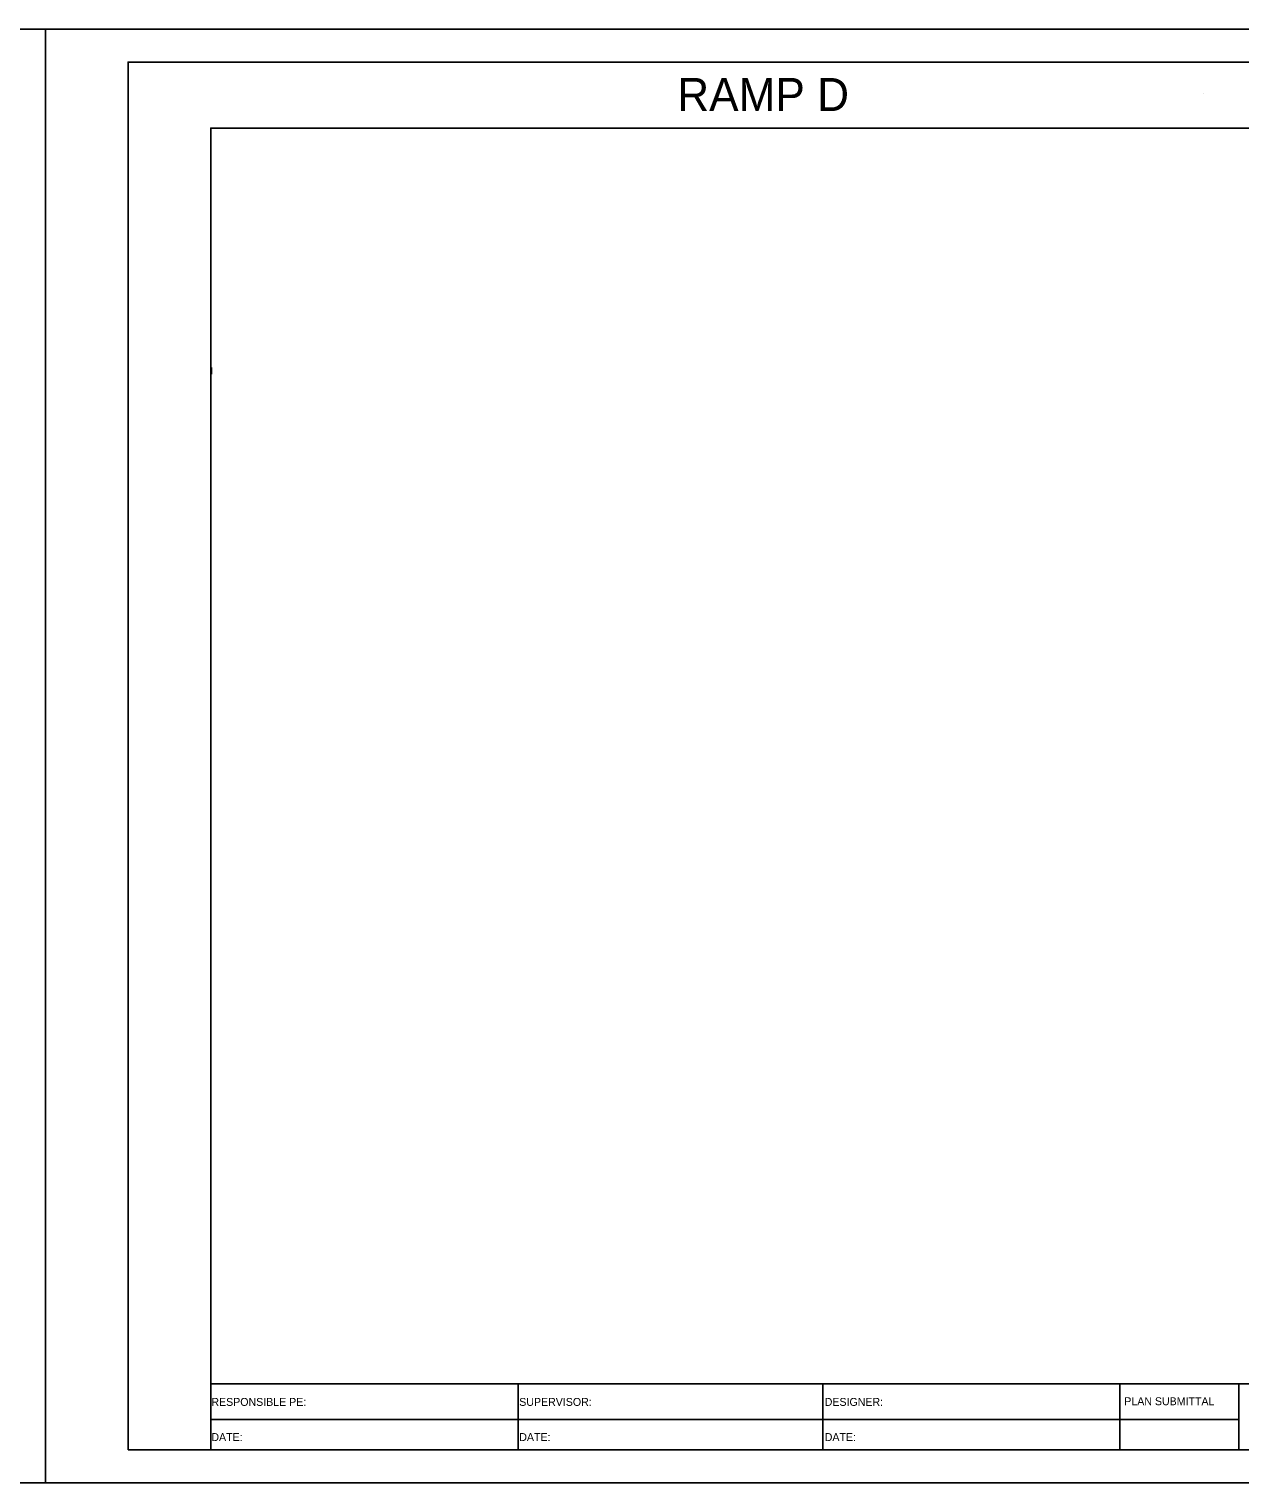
# Model space of a CAD drawing. Extents: x 1797478 to 1804836, y 246529 to 250952.
# Drawn here: x 1802453.5 to 1802636.8, y 250064.4 to 250284.4 of the extents above; entities that cross this region are included whole.
import ezdxf

# ---------------------------------------------------------------- set-up
doc = ezdxf.new("R2010")
doc.units = 0
for name, color, linetype in [('2', 7, 'Continuous'), ('ANNO-SHT', 7, 'Continuous'), ('ANNO-TXT', 7, 'Continuous'), ('AXIS', 7, 'Continuous'), ('DRAINAGE', 7, 'Continuous'), ('Level 1', 7, 'Continuous'), ('Level 62', 7, 'Continuous'), ('SHT-BDR', 7, 'Continuous'), ('SHT-BNDRY', 7, 'Continuous')]:
    doc.layers.add(name, color=color, linetype=linetype)

# ---------------------------------------------------------------- blocks, each defined once
blk = doc.blocks.new('SC47208')
at = {"layer": 'Level 1'}
blk.add_line((0, 0), (0, 0), dxfattribs=at)

msp = doc.modelspace()

# ---------------------------------------------------------------- linework, layer by layer
at = {"layer": '2'}
msp.add_lwpolyline([(1802481.12, 250233.21), (1802481.1, 250232.21)], dxfattribs=at)
msp.add_lwpolyline([(1802481.12, 250233.21), (1802481.1, 250232.21)], dxfattribs=at)
at = {"layer": 'AXIS'}
msp.add_line((1802481, 250189.42), (1802481, 250189.43), dxfattribs=at)
at = {"layer": 'Level 62'}
for points in [[(1802116, 250064.42), (1802456, 250064.42), (1802456, 250284.42), (1802116, 250284.42)], [(1802456, 250064.42), (1802796, 250064.42), (1802796, 250284.42), (1802456, 250284.42)]]:
    msp.add_lwpolyline(points, close=True, dxfattribs=at)
at = {"layer": 'SHT-BDR'}
msp.add_lwpolyline([(1802481, 250079.43), (1802781, 250079.43), (1802781, 250269.43), (1802481, 250269.43)], close=True, dxfattribs=at)
at = {"layer": 'SHT-BNDRY'}
for p, q in [((1802481, 250069.42), (1802481, 250079.43)), ((1802527.52, 250079.43), (1802527.52, 250069.42)), ((1802573.67, 250069.42), (1802573.67, 250079.43)), ((1802618.59, 250069.42), (1802618.59, 250079.43)), ((1802636.63, 250069.42), (1802636.63, 250079.43)), ((1802481, 250074.03), (1802636.63, 250074.03))]:
    msp.add_line(p, q, dxfattribs=at)
msp.add_lwpolyline([(1802468.5, 250069.42), (1802791, 250069.42), (1802791, 250279.42), (1802468.5, 250279.42)], close=True, dxfattribs=at)

# ---------------------------------------------------------------- block references
at = {"layer": 'DRAINAGE', "xscale": 0.2, "yscale": 0.20000000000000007, "rotation": -116.41666666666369}
msp.add_blockref('SC47208', (1802631.32, 250274.62), dxfattribs=at)
msp.add_blockref('SC47208', (1802631.32, 250274.62), dxfattribs=at)

# ---------------------------------------------------------------- texts
at = {"layer": 'ANNO-SHT'}
msp.add_text('                 RAMP D                 ', height=4.9995, rotation=360, dxfattribs=at).set_placement((1802520.04, 250272.02))
at = {"layer": 'ANNO-TXT'}
for s, p in [('RESPONSIBLE PE:', (1802481.1, 250076.08)), ('SUPERVISOR:', (1802527.7, 250076.08)), ('DESIGNER:', (1802573.94, 250076.08)), ('PLAN SUBMITTAL', (1802619.28, 250076.18)), ('DATE:', (1802481.1, 250070.76)), ('DATE:', (1802527.7, 250070.76)), ('DATE:', (1802573.94, 250070.76))]:
    msp.add_text(s, height=1.2, rotation=360, dxfattribs=at).set_placement(p)

doc.saveas('drawing.dxf')
